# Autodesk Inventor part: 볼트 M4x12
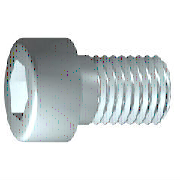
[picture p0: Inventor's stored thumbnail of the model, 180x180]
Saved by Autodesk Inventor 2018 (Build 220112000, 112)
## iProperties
IsCustomPart: 0
Created: 2012-02
Part Number: 볼트 M4x12
Material: 강철, 연강
Description: 6각 소켓 머리 캡 나사
Document SubType Name: Modeling
Standard: ISO 4762
Designer: mduedu
Standard Revision: Fourth edition 2004-03-01
Standards Organization: ISO
Language: ko-KR
Size Designation: M4 x 12
Categories: <MemberInstance><Categories><Category DisplayName="조임쇠" InternalName="e4da775c-781d-43d5-af7c-5136215cf5a6" Mnemonic="FSTN"><Category DisplayName="볼트" InternalN
Density: 7.75 g/cm^3
Appearance: 강철
Author: mduedu
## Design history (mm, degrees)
sketch "스케치1"
  geometry: L1 (-1, 0)-(12, 0); L2 (12, 0)-(12, 2); L3 (12, 2)-(1.75, 2); L4 (1.75, 2)-(1.32, 2); L5 (1.32, 2)-(0, 2); L6 (0, 2)-(0, 3.5); L7 (0, 3.5)-(-4, 3.5); L8 (-4, 3.5)-(-4, 1.732); L9 (-4, 1.732)-(-2, 1.732); L10 (-2, 1.732)-(-1, 0); L11 (-7.2, 0)-(15.2, 0) reference; L12 (0, -0.7)-(0, 4.2) reference; L13 (1.75, 2)-(0, 2)
  constraints: 22 end point, 6 parallel, 2 collinear, 2 perpendicular, 1 horizontal, 1 point on line
  dimensions: "d1" = 10.25 distance from line of L3.end L2 (= GEL); "d2" = 0.42952 distance of L4.end L3.end (computed from GAL); "d3" = 4 distance between parallel lines of L8 L6 (= KOH); "d4" = 2 distance of L8.end L9.end (= INTI); "d5" = 60 deg angle of L10 L1; "d6" = 4 diameter of L3 L1 (= GD); "d7" = 4 diameter of L5 L1 (= BDM); "d8" = 3.4641 diameter of L9 L1 (= 1.1547 x SW); "d9" = 7 diameter of L7 L1 (= KOD); "d26" = 12 distance between parallel lines of L12 L2 (= NLG)
revolve "본체" sketch "스케치1" stored, may be unused: angle "d10" = 90 deg
sketch "스케치2"
  geometry: L1 (0, -4.9)-(0, 4.9) reference; L2 (-4.9, 0)-(4.9, 0) reference; L3 (1.732, 0)-(0.866, -1.5); L4 (0.866, -1.5)-(-0.866, -1.5); L5 (-0.866, -1.5)-(-1.732, 0); L6 (-1.732, 0)-(-0.866, 1.5); L7 (-0.866, 1.5)-(0.866, 1.5); L8 (0.866, 1.5)-(1.732, 0); 2 further points
  constraints: 12 end point, 1 coincident, 1 horizontal alignment, 1 point on line, 12 other
extrude "슬롯" join sketch "스케치2" stored distance "d11" = 10; taper "d12" = 0 deg
workplane "Work Plane1"
fillet "Fillet2" dims "d30" = 0.1 (= R)
body "Solid1"
fillet "모깎기1" dims "d17" = 0.4 (= RR)
feature "스레드" dims "d13" = 10.25 (= GEL), "d14" = 0
chamfer "모따기1" distance "d15" = 0.42941 (= -0.5 x SPD + 0.5 x GD); stored, may be unused: second distance "d16" = 0.42941 (= GUL), angle "d27" = 45 deg
other parameters: "GD" = 4 [user parameter; used in 2 equation terms], "NLG" = 12 [user parameter; used in 1 equation term], "GEL" = 10.25 [user parameter; used in 2 equation terms], "KOD" = 7 [user parameter; used in 1 equation term], "KOH" = 4 [user parameter; used in 1 equation term], "INTI" = 2 [user parameter; used in 1 equation term], "GAL" = 0.42941 (= 0.61345 x PTC) [user parameter; used in 1 equation term], "GUL" = 0.42941 (= 0.61345 x PTC) [user parameter; used in 1 equation term], "BDM" = 4 (= NND) [user parameter; used in 1 equation term], "SW" = 3 [user parameter; used in 2 equation terms], "RR" = 0.4 [user parameter; used in 1 equation term], "SPD" = 3.14117 (= NND - 1.2269 x PTC) [user parameter; used in 1 equation term], "d19" = 0, "d28" = 0, "d29" = 0, "R" = 0.1 [user parameter; used in 1 equation term], "TOA" = 30 deg [user parameter], "GD1" = 3.14117 (= THREADDIA - 1.2269 x PTC) [user parameter], "THREADDIA" = 4 [user parameter; used in 1 equation term], "FAWI" = 45 deg [user parameter], "TPU" = 14.28571 (computed from PTC) [user parameter], "PTC" = 0.7 [user parameter; used in 5 equation terms], "NND" = 4 [user parameter; used in 2 equation terms], "E0" = 3.465 (= 1.155 x SW) [user parameter]
